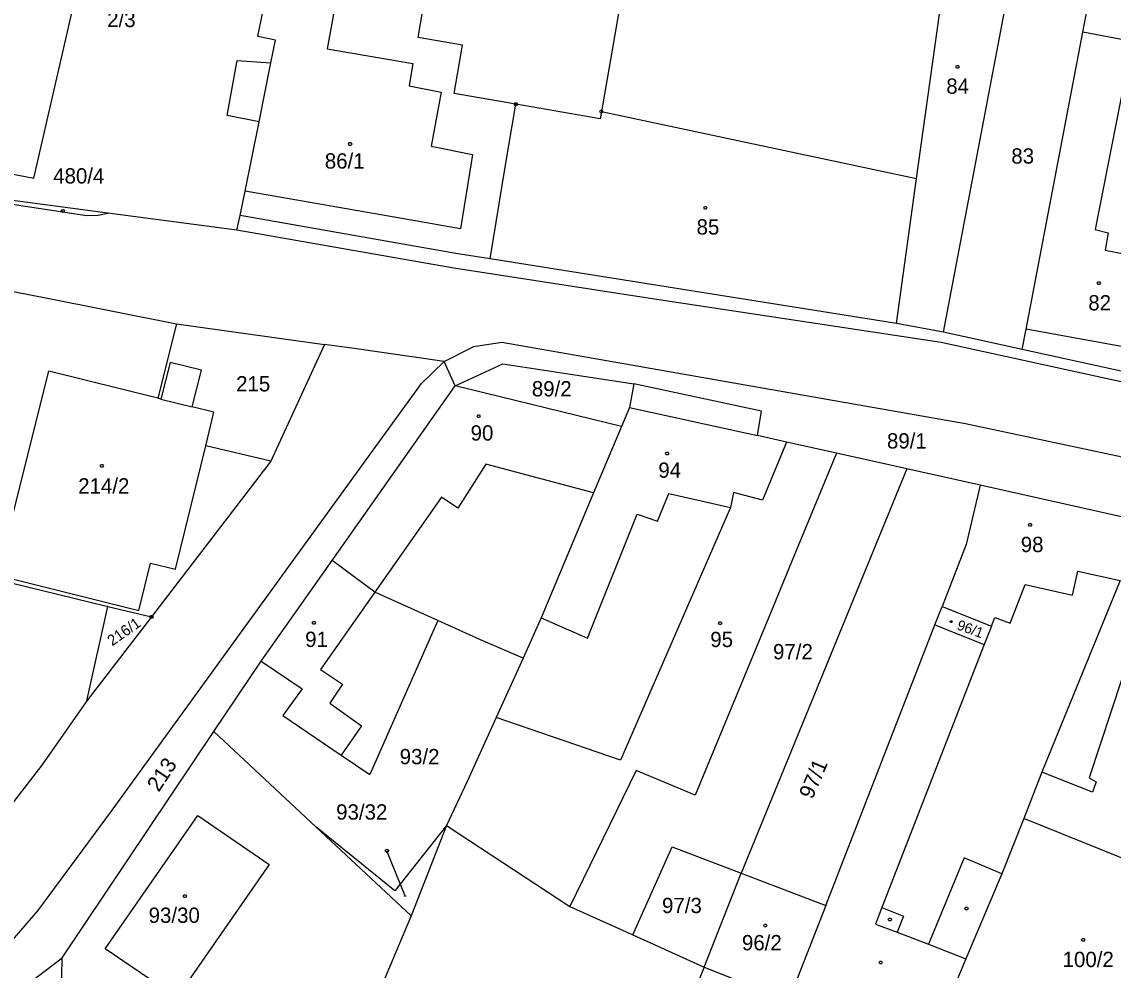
# Model space of a CAD drawing. Extents: x -634640 to -629202, y -1196156 to -1190068.
# Drawn here: x -631489.7 to -631368.4, y -1192728.1 to -1192622.8 of the extents above; entities that cross this region are included whole.
import ezdxf

# ---------------------------------------------------------------- set-up
doc = ezdxf.new("R2010")
doc.units = 0
for name, color, linetype in [('Vrstva 1', 7, 'Continuous'), ('Vrstva 2', 7, 'Continuous'), ('Vrstva 3', 7, 'Continuous'), ('Vrstva 4', 7, 'Continuous'), ('Vrstva 5', 7, 'Continuous'), ('Vrstva 7', 7, 'Continuous'), ('Vrstva 8', 7, 'Continuous')]:
    doc.layers.add(name, color=color, linetype=linetype)

msp = doc.modelspace()

# ---------------------------------------------------------------- linework, layer by layer
at = {"layer": 'Vrstva 1'}
for p, q in [((-631390.28, -1192640.16), (-631385.52, -1192605.93)), ((-631387.27, -1192657.24), (-631378.89, -1192613.08)), ((-631371.82, -1192623.91), (-631369.61, -1192612.61)), ((-631488.33, -1192640.14), (-631484.08, -1192621.6)), ((-631463.44, -1192624.4), (-631462.89, -1192621.66)), ((-631461.49, -1192624.82), (-631463.44, -1192624.4)), ((-631378.09, -1192656.92), (-631371.82, -1192623.91)), ((-631461.99, -1192627.32), (-631461.49, -1192624.82)), ((-631466.86, -1192633.18), (-631465.73, -1192627.06)), ((-631465.73, -1192627.06), (-631461.99, -1192627.32)), ((-631435.99, -1192638.91), (-631434.79, -1192631.92)), ((-631425.29, -1192632.74), (-631390.28, -1192640.16)), ((-631463.31, -1192633.89), (-631466.86, -1192633.18)), ((-631464.85, -1192641.59), (-631463.31, -1192633.89)), ((-631501.41, -1192637.66), (-631488.33, -1192640.14)), ((-631437.64, -1192649.1), (-631435.99, -1192638.91)), ((-631392.52, -1192656.29), (-631390.28, -1192640.16)), ((-631480.12, -1192644.03), (-631502.92, -1192641.02)), ((-631465.4, -1192644.27), (-631464.85, -1192641.59)), ((-631465.79, -1192645.92), (-631480.12, -1192644.03)), ((-631465.79, -1192645.92), (-631465.4, -1192644.27)), ((-631441.45, -1192648.49), (-631465.4, -1192644.27)), ((-631441.67, -1192650.13), (-631465.79, -1192645.92)), ((-631437.64, -1192649.1), (-631441.45, -1192648.49)), ((-631392.52, -1192656.29), (-631437.64, -1192649.1)), ((-631419.37, -1192653.57), (-631441.67, -1192650.13)), ((-631492, -1192652.45), (-631487.19, -1192653.4)), ((-631487.19, -1192653.4), (-631472.48, -1192656.32)), ((-631387.55, -1192658.39), (-631419.37, -1192653.57)), ((-631472.48, -1192656.32), (-631474.56, -1192664.59)), ((-631472.48, -1192656.32), (-631456.04, -1192658.61)), ((-631387.27, -1192657.24), (-631392.52, -1192656.29)), ((-631378.54, -1192659.16), (-631378.09, -1192656.92)), ((-631439.46, -1192658.83), (-631436.35, -1192658.35)), ((-631436.35, -1192658.35), (-631421.13, -1192661.02)), ((-631345.12, -1192667.68), (-631387.55, -1192658.39)), ((-631378.54, -1192659.16), (-631387.27, -1192657.24)), ((-631456.04, -1192658.61), (-631462, -1192671.56)), ((-631452.76, -1192659.07), (-631456.04, -1192658.61)), ((-631442.75, -1192660.49), (-631452.76, -1192659.07)), ((-631442.75, -1192660.49), (-631439.46, -1192658.83)), ((-631363.68, -1192662.42), (-631378.54, -1192659.16)), ((-631473.2, -1192660.61), (-631474.22, -1192664.67)), ((-631469.72, -1192661.48), (-631473.2, -1192660.61)), ((-631445.26, -1192662.93), (-631442.75, -1192660.49)), ((-631441.52, -1192663.19), (-631442.75, -1192660.49)), ((-631441.52, -1192663.19), (-631436.23, -1192660.76)), ((-631436.23, -1192660.76), (-631421.69, -1192662.97)), ((-631470.74, -1192665.54), (-631469.72, -1192661.48)), ((-631421.13, -1192661.02), (-631384.86, -1192667.38)), ((-631479.83, -1192710.61), (-631445.26, -1192662.93)), ((-631455.21, -1192682.62), (-631441.52, -1192663.19)), ((-631423.06, -1192667.71), (-631441.52, -1192663.19)), ((-631421.69, -1192662.97), (-631422.16, -1192665.6)), ((-631407.5, -1192666.03), (-631421.69, -1192662.97)), ((-631474.22, -1192664.67), (-631474.56, -1192664.59)), ((-631468.32, -1192666.15), (-631470.74, -1192665.54)), ((-631422.16, -1192665.6), (-631423.06, -1192667.71)), ((-631469.23, -1192669.87), (-631468.32, -1192666.15)), ((-631407.96, -1192668.74), (-631407.5, -1192666.03)), ((-631423.06, -1192667.71), (-631426.15, -1192675.08)), ((-631384.86, -1192667.38), (-631346.18, -1192675.61)), ((-631404.74, -1192669.45), (-631407.96, -1192668.74)), ((-631462, -1192671.56), (-631469.23, -1192669.87)), ((-631404.74, -1192669.45), (-631407.38, -1192675.92)), ((-631399.17, -1192670.68), (-631404.74, -1192669.45)), ((-631462, -1192671.56), (-631475.27, -1192688.88)), ((-631399.17, -1192670.68), (-631403.88, -1192682.07)), ((-631391.34, -1192672.43), (-631399.17, -1192670.68)), ((-631391.34, -1192672.43), (-631409.76, -1192717.35)), ((-631383.23, -1192674.24), (-631391.34, -1192672.43)), ((-631426.15, -1192675.08), (-631431.97, -1192688.97)), ((-631410.63, -1192675.06), (-631410.96, -1192676.72)), ((-631407.38, -1192675.92), (-631410.63, -1192675.06)), ((-631383.23, -1192674.24), (-631384.77, -1192680.85)), ((-631365.05, -1192678.33), (-631383.23, -1192674.24)), ((-631410.96, -1192676.72), (-631423.16, -1192704.8)), ((-631384.77, -1192680.85), (-631387.44, -1192687.72)), ((-631463.09, -1192693.78), (-631455.21, -1192682.62)), ((-631450.44, -1192686.14), (-631455.21, -1192682.62)), ((-631403.88, -1192682.07), (-631406.25, -1192687.84)), ((-631480.39, -1192687.68), (-631495.95, -1192683.91)), ((-631367.66, -1192684.83), (-631376.35, -1192706.11)), ((-631443.46, -1192689.29), (-631450.44, -1192686.14)), ((-631482.43, -1192698.21), (-631480.12, -1192687.71)), ((-631480.12, -1192687.71), (-631480.39, -1192687.68)), ((-631480.12, -1192687.71), (-631475.27, -1192688.88)), ((-631406.25, -1192687.84), (-631414.86, -1192708.7)), ((-631388.23, -1192689.75), (-631387.44, -1192687.72)), ((-631387.44, -1192687.72), (-631381.97, -1192689.92)), ((-631475.27, -1192688.88), (-631482.43, -1192698.21)), ((-631443.46, -1192689.29), (-631451.02, -1192706.4)), ((-631438.72, -1192691.44), (-631443.46, -1192689.29)), ((-631431.97, -1192688.97), (-631433.99, -1192693.45)), ((-631400.34, -1192720.95), (-631388.23, -1192689.75)), ((-631388.23, -1192689.75), (-631382.75, -1192691.94)), ((-631381.97, -1192689.92), (-631382.75, -1192691.94)), ((-631433.99, -1192693.45), (-631438.72, -1192691.44)), ((-631382.75, -1192691.94), (-631394.14, -1192721.18)), ((-631433.99, -1192693.45), (-631436.98, -1192700.07)), ((-631468.33, -1192701.6), (-631463.09, -1192693.78)), ((-631463.09, -1192693.78), (-631458.54, -1192696.87)), ((-631458.54, -1192696.87), (-631460.66, -1192699.84)), ((-631482.43, -1192698.21), (-631487.46, -1192705.36)), ((-631460.66, -1192699.84), (-631454.21, -1192704.23)), ((-631436.98, -1192700.07), (-631440.18, -1192707.17)), ((-631423.16, -1192704.8), (-631436.98, -1192700.07)), ((-631485.2, -1192726.74), (-631468.33, -1192701.6)), ((-631468.33, -1192701.6), (-631456.99, -1192712.21)), ((-631454.21, -1192704.23), (-631451.02, -1192706.4)), ((-631487.46, -1192705.36), (-631498.36, -1192719.36)), ((-631421.44, -1192705.96), (-631428.81, -1192721.04)), ((-631414.86, -1192708.7), (-631421.44, -1192705.96)), ((-631376.35, -1192706.11), (-631378.38, -1192711.29)), ((-631440.18, -1192707.17), (-631442.48, -1192712.05)), ((-631487.9, -1192721.54), (-631479.83, -1192710.61)), ((-631378.38, -1192711.29), (-631380.79, -1192717.42)), ((-631356.56, -1192720.09), (-631378.38, -1192711.29)), ((-631456.99, -1192712.21), (-631446.43, -1192722.09)), ((-631442.48, -1192712.05), (-631446.43, -1192722.09)), ((-631442.48, -1192712.05), (-631428.81, -1192721.04)), ((-631421.81, -1192724.2), (-631417.42, -1192714.42)), ((-631417.42, -1192714.42), (-631409.76, -1192717.35)), ((-631413.88, -1192727.78), (-631409.76, -1192717.35)), ((-631409.76, -1192717.35), (-631400.34, -1192720.95)), ((-631380.79, -1192717.42), (-631384.81, -1192726.88)), ((-631428.81, -1192721.04), (-631421.81, -1192724.2)), ((-631400.34, -1192720.95), (-631404.48, -1192731.49)), ((-631394.14, -1192721.18), (-631394.85, -1192723.01)), ((-631500.14, -1192735.72), (-631487.9, -1192721.54)), ((-631446.43, -1192722.09), (-631453.01, -1192737.63)), ((-631394.85, -1192723.01), (-631392.45, -1192723.91)), ((-631421.81, -1192724.2), (-631413.88, -1192727.78)), ((-631392.45, -1192723.91), (-631388.95, -1192725.23)), ((-631388.95, -1192725.23), (-631384.81, -1192726.88)), ((-631498.79, -1192737.08), (-631485.2, -1192726.74)), ((-631485.26, -1192732.88), (-631485.2, -1192726.74)), ((-631384.81, -1192726.88), (-631387.28, -1192732.83)), ((-631413.88, -1192727.78), (-631417.89, -1192737.71)), ((-631413.88, -1192727.78), (-631404.48, -1192731.49))]:
    msp.add_line(p, q, dxfattribs=at)
for points in [[(-631441.99, -1192603.31), (-631420.79, -1192606.86), (-631425.29, -1192632.74)], [(-631434.79, -1192631.92), (-631441.64, -1192630.74), (-631440.71, -1192625.36), (-631445.64, -1192624.51), (-631443.72, -1192613.19)], [(-631425.29, -1192632.74), (-631425.43, -1192633.54), (-631434.79, -1192631.92)], [(-631502.92, -1192641.02), (-631501.98, -1192641.32), (-631482.44, -1192644.3), (-631481.2, -1192644.25), (-631480.12, -1192644.03)], [(-631470.12, -1192710.93), (-631462.2, -1192716.4), (-631472.46, -1192731.17), (-631480.39, -1192725.76), (-631470.12, -1192710.93)], [(-631442.48, -1192712.05), (-631448.24, -1192719.32), (-631456.99, -1192712.21)]]:
    msp.add_lwpolyline(points, dxfattribs=at)
at = {"layer": 'Vrstva 3'}
for points in [[(-631385.65, -1192627.61), (-631385.56, -1192627.76), (-631385.65, -1192627.91), (-631385.83, -1192627.91), (-631385.92, -1192627.76), (-631385.83, -1192627.61), (-631385.65, -1192627.61)], [(-631413.65, -1192643.29), (-631413.56, -1192643.44), (-631413.65, -1192643.59), (-631413.83, -1192643.59), (-631413.92, -1192643.44), (-631413.83, -1192643.29), (-631413.65, -1192643.29)], [(-631412, -1192689.41), (-631411.91, -1192689.56), (-631412, -1192689.71), (-631412.18, -1192689.71), (-631412.27, -1192689.56), (-631412.18, -1192689.41), (-631412, -1192689.41)], [(-631371.69, -1192724.6), (-631371.6, -1192724.75), (-631371.69, -1192724.9), (-631371.87, -1192724.9), (-631371.96, -1192724.75), (-631371.87, -1192724.6), (-631371.69, -1192724.6)]]:
    msp.add_lwpolyline(points, dxfattribs=at)
at = {"layer": 'Vrstva 4'}
for p, q in [((-631453.13, -1192611.55), (-631455.75, -1192625.76)), ((-631366.33, -1192624.94), (-631371.82, -1192623.91)), ((-631366.33, -1192624.94), (-631370.44, -1192645.84)), ((-631455.75, -1192625.76), (-631446.25, -1192627.38)), ((-631463.31, -1192633.89), (-631461.99, -1192627.32)), ((-631446.25, -1192627.38), (-631446.63, -1192629.89)), ((-631446.63, -1192629.89), (-631443.07, -1192630.58)), ((-631443.07, -1192630.58), (-631444.18, -1192636.58)), ((-631444.18, -1192636.58), (-631439.59, -1192637.52)), ((-631439.59, -1192637.52), (-631439.7, -1192638.2)), ((-631439.7, -1192638.2), (-631440.92, -1192645.76)), ((-631446.61, -1192644.77), (-631464.85, -1192641.59)), ((-631440.92, -1192645.76), (-631446.61, -1192644.77)), ((-631370.44, -1192645.84), (-631369.01, -1192646.2)), ((-631369.01, -1192646.2), (-631369.34, -1192648.15)), ((-631369.34, -1192648.15), (-631364, -1192649.18)), ((-631363.12, -1192659.62), (-631378.09, -1192656.92)), ((-631490.94, -1192678.58), (-631486.66, -1192661.56)), ((-631474.56, -1192664.59), (-631486.66, -1192661.56)), ((-631474.22, -1192664.67), (-631470.74, -1192665.54)), ((-631422.16, -1192665.6), (-631407.96, -1192668.74)), ((-631472.6, -1192683.58), (-631469.23, -1192669.87)), ((-631438.13, -1192671.9), (-631441.25, -1192676.81)), ((-631426.15, -1192675.08), (-631438.13, -1192671.9)), ((-631419.04, -1192678.24), (-631417.79, -1192675.15)), ((-631417.79, -1192675.15), (-631410.96, -1192676.72)), ((-631443.03, -1192675.58), (-631450.44, -1192686.14)), ((-631441.25, -1192676.81), (-631443.03, -1192675.58)), ((-631426.83, -1192691.23), (-631421.32, -1192677.48)), ((-631421.32, -1192677.48), (-631419.04, -1192678.24)), ((-631497.97, -1192682.85), (-631476.68, -1192688.16)), ((-631476.68, -1192688.16), (-631475.36, -1192682.89)), ((-631475.36, -1192682.89), (-631472.6, -1192683.58)), ((-631372.94, -1192686.45), (-631372.37, -1192683.81)), ((-631372.37, -1192683.81), (-631367.66, -1192684.83)), ((-631450.44, -1192686.14), (-631456.47, -1192694.72)), ((-631379.89, -1192689.57), (-631378.22, -1192685.27)), ((-631378.22, -1192685.27), (-631372.94, -1192686.45)), ((-631431.97, -1192688.97), (-631426.83, -1192691.23)), ((-631381.97, -1192689.92), (-631381.59, -1192688.95)), ((-631381.59, -1192688.95), (-631379.89, -1192689.57)), ((-631366.21, -1192691.93), (-631371.1, -1192706.74)), ((-631456.47, -1192694.72), (-631454.03, -1192696.34)), ((-631454.03, -1192696.34), (-631455.46, -1192698.47)), ((-631455.46, -1192698.47), (-631451.93, -1192700.97)), ((-631451.93, -1192700.97), (-631454.21, -1192704.23)), ((-631370.75, -1192708.34), (-631376.35, -1192706.11)), ((-631371.1, -1192706.74), (-631370.33, -1192707.19)), ((-631370.33, -1192707.19), (-631370.75, -1192708.34)), ((-631385, -1192715.65), (-631388.95, -1192725.23)), ((-631380.79, -1192717.42), (-631385, -1192715.65)), ((-631394.14, -1192721.18), (-631391.72, -1192722.13)), ((-631391.72, -1192722.13), (-631392.45, -1192723.91))]:
    msp.add_line(p, q, dxfattribs=at)
at = {"layer": 'Vrstva 5'}
for points in [[(-631453.1, -1192636.19), (-631453.01, -1192636.34), (-631453.1, -1192636.49), (-631453.28, -1192636.49), (-631453.37, -1192636.34), (-631453.28, -1192636.19), (-631453.1, -1192636.19)], [(-631369.94, -1192651.64), (-631369.85, -1192651.79), (-631369.94, -1192651.94), (-631370.12, -1192651.94), (-631370.21, -1192651.79), (-631370.12, -1192651.64), (-631369.94, -1192651.64)], [(-631438.83, -1192666.41), (-631438.74, -1192666.56), (-631438.83, -1192666.71), (-631439.01, -1192666.71), (-631439.1, -1192666.56), (-631439.01, -1192666.41), (-631438.83, -1192666.41)], [(-631417.88, -1192670.56), (-631417.79, -1192670.71), (-631417.88, -1192670.86), (-631418.06, -1192670.86), (-631418.15, -1192670.71), (-631418.06, -1192670.56), (-631417.88, -1192670.56)], [(-631480.7, -1192671.96), (-631480.61, -1192672.11), (-631480.7, -1192672.26), (-631480.88, -1192672.26), (-631480.97, -1192672.11), (-631480.88, -1192671.96), (-631480.7, -1192671.96)], [(-631377.57, -1192678.5), (-631377.48, -1192678.65), (-631377.57, -1192678.8), (-631377.75, -1192678.8), (-631377.84, -1192678.65), (-631377.75, -1192678.5), (-631377.57, -1192678.5)], [(-631457.15, -1192689.39), (-631457.06, -1192689.54), (-631457.15, -1192689.69), (-631457.33, -1192689.69), (-631457.42, -1192689.54), (-631457.33, -1192689.39), (-631457.15, -1192689.39)], [(-631386.37, -1192689.31), (-631386.309, -1192689.41), (-631386.37, -1192689.51), (-631386.49, -1192689.51), (-631386.551, -1192689.41), (-631386.49, -1192689.31), (-631386.37, -1192689.31)], [(-631471.48, -1192719.75), (-631471.39, -1192719.9), (-631471.48, -1192720.05), (-631471.66, -1192720.05), (-631471.75, -1192719.9), (-631471.66, -1192719.75), (-631471.48, -1192719.75)], [(-631384.63, -1192721.13), (-631384.54, -1192721.28), (-631384.63, -1192721.43), (-631384.81, -1192721.43), (-631384.9, -1192721.28), (-631384.81, -1192721.13), (-631384.63, -1192721.13)], [(-631393.17, -1192722.35), (-631393.08, -1192722.5), (-631393.17, -1192722.65), (-631393.35, -1192722.65), (-631393.44, -1192722.5), (-631393.35, -1192722.35), (-631393.17, -1192722.35)], [(-631406.99, -1192723.01), (-631406.9, -1192723.16), (-631406.99, -1192723.31), (-631407.17, -1192723.31), (-631407.26, -1192723.16), (-631407.17, -1192723.01), (-631406.99, -1192723.01)], [(-631394.18, -1192727.11), (-631394.09, -1192727.26), (-631394.18, -1192727.41), (-631394.36, -1192727.41), (-631394.45, -1192727.26), (-631394.36, -1192727.11), (-631394.18, -1192727.11)]]:
    msp.add_lwpolyline(points, dxfattribs=at)
at = {"layer": 'Vrstva 7'}
for p, q in [((-631485.18, -1192643.79), (-631485.08, -1192643.77)), ((-631447.03, -1192719.96), (-631449.11, -1192714.87))]:
    msp.add_line(p, q, dxfattribs=at)
for points in [[(-631484.912, -1192643.722), (-631484.949, -1192643.893), (-631485.117, -1192643.941), (-631485.248, -1192643.818), (-631485.211, -1192643.647), (-631485.043, -1192643.599), (-631484.912, -1192643.722)], [(-631449.084, -1192714.697), (-631448.943, -1192714.802), (-631448.97, -1192714.975), (-631449.136, -1192715.043), (-631449.277, -1192714.938), (-631449.25, -1192714.765), (-631449.084, -1192714.697)]]:
    msp.add_lwpolyline(points, dxfattribs=at)
at = {"layer": 'Vrstva 8'}
for points in [[(-631434.7, -1192631.77), (-631434.61, -1192631.92), (-631434.7, -1192632.07), (-631434.88, -1192632.07), (-631434.97, -1192631.92), (-631434.88, -1192631.77), (-631434.7, -1192631.77)], [(-631425.2, -1192632.59), (-631425.11, -1192632.74), (-631425.2, -1192632.89), (-631425.38, -1192632.89), (-631425.47, -1192632.74), (-631425.38, -1192632.59), (-631425.2, -1192632.59)], [(-631475.18, -1192688.73), (-631475.09, -1192688.88), (-631475.18, -1192689.03), (-631475.36, -1192689.03), (-631475.45, -1192688.88), (-631475.36, -1192688.73), (-631475.18, -1192688.73)]]:
    msp.add_lwpolyline(points, dxfattribs=at)

# ---------------------------------------------------------------- texts
at = {"layer": 'Vrstva 2'}
for s, height, p in [('2/3', 1.7, (-631480.183, -1192623.35)), ('84', 1.7, (-631386.973, -1192630.76)), ('86/1', 1.7, (-631456.01, -1192639.07)), ('83', 1.7, (-631379.753, -1192638.52)), ('480/4', 0.1, (-631485.414, -1192643.79)), ('85', 1.7, (-631414.713, -1192646.4)), ('82', 1.7, (-631371.203, -1192654.83)), ('215', 1.7, (-631465.863, -1192663.83)), ('89/2', 1.7, (-631433.013, -1192664.38)), ('90', 1.7, (-631439.813, -1192669.29)), ('89/1', 1.7, (-631393.563, -1192670.17)), ('94', 1.7, (-631418.963, -1192673.42)), ('214/2', 1.7, (-631483.403, -1192675.17)), ('98', 1.7, (-631378.703, -1192681.68)), ('91', 1.7, (-631458.193, -1192692.22)), ('95', 1.7, (-631413.193, -1192692.23)), ('97/2', 1.7, (-631406.223, -1192693.59)), ('93/2', 1.7, (-631447.693, -1192705.25)), ('93/32', 0.1, (-631447.258, -1192719.96)), ('97/3', 1.7, (-631418.553, -1192721.79)), ('93/30', 1.7, (-631475.582, -1192722.87)), ('96/2', 1.7, (-631409.673, -1192725.92)), ('100/2', 1.7, (-631374.057, -1192727.78))]:
    msp.add_text(s, height=height, dxfattribs=at).set_placement(p)
for s, height, rotation, p in [('216/1', 1.2, 35.17961, (-631479.623, -1192692.153)), ('96/1', 1.14, 339.87856, (-631385.891, -1192690.235)), ('213', 1.7, 56.32175, (-631474.468, -1192708.422)), ('97/1', 1.7, 66.80688, (-631401.847, -1192709.222))]:
    msp.add_text(s, height=height, rotation=rotation, dxfattribs=at).set_placement(p)
at = {"layer": 'Vrstva 7'}
for s, p in [('480/4', (-631486.182, -1192640.73)), ('93/32', (-631454.748, -1192711.4))]:
    msp.add_text(s, height=1.7, dxfattribs=at).set_placement(p)

doc.saveas('drawing.dxf')
